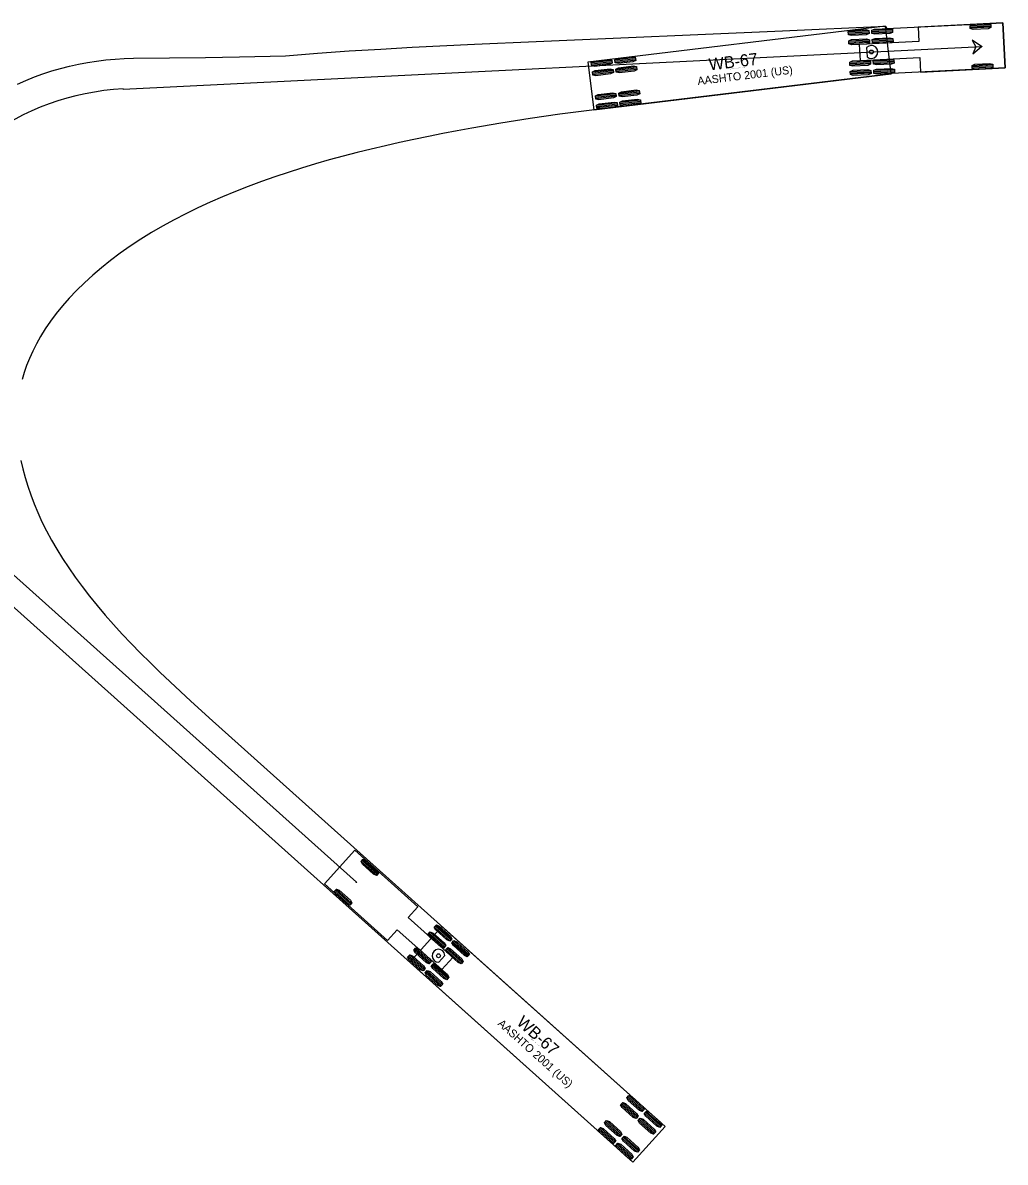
# Model space of a CAD drawing. Extents: x 1639988 to 1641860, y 841974 to 844187.
# Drawn here: x 1641686.5 to 1641860.3, y 841973.9 to 842175.6 of the extents above; entities that cross this region are included whole.
import ezdxf

# ---------------------------------------------------------------- set-up
doc = ezdxf.new("R2010")
doc.units = 0
doc.layers.add('Scratch_Level_1', color=7, linetype='Continuous')

msp = doc.modelspace()

# ---------------------------------------------------------------- linework, layer by layer
at = {"layer": 'Scratch_Level_1'}
for p, q in [((1641859.9, 842175.59), (1641844.91, 842174.84)), ((1641860.29, 842167.6), (1641859.9, 842175.59)), ((1641859.9, 842175.59), (1641859.9, 842175.59)), ((1641839.09, 842175.01), (1641786.47, 842168.65)), ((1641836.19, 842174.18), (1641832.52, 842174)), ((1641836.2, 842173.95), (1641832.54, 842173.77)), ((1641836.21, 842173.72), (1641832.55, 842173.54)), ((1641840.35, 842174.39), (1641836.69, 842174.21)), ((1641840.36, 842174.16), (1641836.7, 842173.98)), ((1641840.37, 842173.93), (1641836.71, 842173.75)), ((1641840.11, 842166.57), (1641839.09, 842175.01)), ((1641839.09, 842175.01), (1641839.09, 842175.01)), ((1641844.91, 842174.84), (1641845.04, 842172.28)), ((1641857.74, 842175.25), (1641854.08, 842175.07)), ((1641857.75, 842175.02), (1641854.09, 842174.84)), ((1641857.77, 842174.8), (1641854.1, 842174.61)), ((1641836.27, 842172.53), (1641832.61, 842172.35)), ((1641836.28, 842172.3), (1641832.62, 842172.12)), ((1641836.29, 842172.08), (1641832.63, 842171.89)), ((1641845.04, 842172.28), (1641834.47, 842171.76)), ((1641834.47, 842171.76), (1641834.61, 842168.89)), ((1641840.43, 842172.74), (1641836.77, 842172.56)), ((1641840.44, 842172.51), (1641836.78, 842172.33)), ((1641840.45, 842172.28), (1641836.79, 842172.1)), ((1641704.24, 842163.87), (1641856.1, 842171.4)), ((1641794.86, 842169.43), (1641791.22, 842168.99)), ((1641834.61, 842168.89), (1641845.18, 842169.42)), ((1641835.78, 842171.19), (1641835.86, 842169.58)), ((1641845.18, 842169.42), (1641845.31, 842166.85)), ((1641786.47, 842168.65), (1641787.49, 842160.21)), ((1641790.72, 842168.93), (1641787.08, 842168.49)), ((1641790.75, 842168.7), (1641787.11, 842168.26)), ((1641790.78, 842168.47), (1641787.14, 842168.03)), ((1641794.89, 842169.2), (1641791.24, 842168.76)), ((1641794.91, 842168.97), (1641791.27, 842168.53)), ((1641795.06, 842167.79), (1641791.42, 842167.35)), ((1641795.08, 842167.56), (1641791.44, 842167.12)), ((1641836.46, 842168.75), (1641832.79, 842168.57)), ((1641836.47, 842168.53), (1641832.81, 842168.34)), ((1641836.48, 842168.3), (1641832.82, 842168.11)), ((1641840.62, 842168.96), (1641836.96, 842168.78)), ((1641840.63, 842168.73), (1641836.97, 842168.55)), ((1641840.64, 842168.5), (1641836.98, 842168.32)), ((1641845.31, 842166.85), (1641860.29, 842167.6)), ((1641858.09, 842168.18), (1641854.43, 842168)), ((1641858.11, 842167.95), (1641854.44, 842167.77)), ((1641858.12, 842167.72), (1641854.45, 842167.54)), ((1641790.92, 842167.29), (1641787.28, 842166.85)), ((1641790.95, 842167.06), (1641787.31, 842166.62)), ((1641790.97, 842166.84), (1641787.33, 842166.4)), ((1641787.49, 842160.21), (1641840.11, 842166.57)), ((1641795.11, 842167.34), (1641791.47, 842166.9)), ((1641836.54, 842167.11), (1641832.88, 842166.92)), ((1641836.55, 842166.88), (1641832.89, 842166.7)), ((1641836.56, 842166.65), (1641832.9, 842166.47)), ((1641840.7, 842167.31), (1641837.04, 842167.13)), ((1641840.71, 842167.08), (1641837.05, 842166.9)), ((1641840.72, 842166.86), (1641837.06, 842166.67)), ((1641795.57, 842163.54), (1641791.93, 842163.1)), ((1641791.43, 842163.04), (1641787.79, 842162.6)), ((1641791.46, 842162.81), (1641787.82, 842162.37)), ((1641791.49, 842162.58), (1641787.85, 842162.14)), ((1641791.63, 842161.4), (1641787.99, 842160.96)), ((1641795.6, 842163.31), (1641791.96, 842162.87)), ((1641795.62, 842163.08), (1641791.98, 842162.64)), ((1641795.77, 842161.9), (1641792.13, 842161.46)), ((1641795.8, 842161.67), (1641792.15, 842161.23)), ((1641795.82, 842161.45), (1641792.18, 842161.01)), ((1641791.66, 842161.17), (1641788.02, 842160.73)), ((1641791.69, 842160.95), (1641788.05, 842160.51)), ((1641745.52, 842023.49), (1641676.43, 842085.42)), ((1641745.21, 842029.14), (1641739.87, 842023.18)), ((1641756.38, 842019.13), (1641745.21, 842029.14)), ((1641746.37, 842027.18), (1641749.1, 842024.74)), ((1641746.52, 842027.35), (1641749.25, 842024.91)), ((1641746.67, 842027.53), (1641749.4, 842025.08)), ((1641739.87, 842023.18), (1641751.04, 842013.17)), ((1641739.87, 842023.18), (1641739.87, 842023.18)), ((1641741.94, 842022.25), (1641744.67, 842019.8)), ((1641741.64, 842021.91), (1641744.37, 842019.46)), ((1641741.79, 842022.08), (1641744.52, 842019.63)), ((1641754.67, 842017.22), (1641756.38, 842019.13)), ((1641762.55, 842010.16), (1641754.67, 842017.22)), ((1641751.04, 842013.17), (1641752.75, 842015.08)), ((1641752.75, 842015.08), (1641760.64, 842008.02)), ((1641760.64, 842015.65), (1641754.97, 842009.32)), ((1641758.23, 842014.33), (1641760.96, 842011.88)), ((1641758.39, 842014.5), (1641761.12, 842012.05)), ((1641758.54, 842014.67), (1641761.27, 842012.22)), ((1641759.34, 842015.56), (1641762.07, 842013.11)), ((1641759.49, 842015.73), (1641762.22, 842013.28)), ((1641759.64, 842015.9), (1641762.37, 842013.45)), ((1641800.11, 841980.27), (1641760.64, 842015.65)), ((1641762.44, 842012.78), (1641765.17, 842010.33)), ((1641762.59, 842012.95), (1641765.32, 842010.5)), ((1641762.74, 842013.12), (1641765.47, 842010.67)), ((1641754.61, 842010.28), (1641757.34, 842007.84)), ((1641754.76, 842010.46), (1641757.49, 842008.01)), ((1641754.91, 842010.63), (1641757.64, 842008.18)), ((1641755.71, 842011.51), (1641758.44, 842009.07)), ((1641755.86, 842011.68), (1641758.59, 842009.24)), ((1641756.01, 842011.85), (1641758.75, 842009.41)), ((1641760.1, 842009.34), (1641761.18, 842010.54)), ((1641760.64, 842008.02), (1641762.55, 842010.16)), ((1641761.34, 842011.55), (1641764.07, 842009.1)), ((1641761.49, 842011.72), (1641764.22, 842009.27)), ((1641761.64, 842011.89), (1641764.37, 842009.44)), ((1641754.97, 842009.32), (1641794.44, 841973.94)), ((1641754.97, 842009.32), (1641754.97, 842009.32)), ((1641758.81, 842008.73), (1641761.54, 842006.29)), ((1641758.96, 842008.9), (1641761.7, 842006.46)), ((1641759.12, 842009.07), (1641761.85, 842006.63)), ((1641757.71, 842007.5), (1641760.44, 842005.06)), ((1641757.86, 842007.67), (1641760.59, 842005.23)), ((1641758.02, 842007.84), (1641760.75, 842005.4)), ((1641792.28, 841984.15), (1641795.01, 841981.7)), ((1641792.44, 841984.32), (1641795.17, 841981.87)), ((1641792.59, 841984.49), (1641795.32, 841982.04)), ((1641793.38, 841985.38), (1641796.11, 841982.93)), ((1641793.54, 841985.55), (1641796.27, 841983.1)), ((1641793.69, 841985.72), (1641796.42, 841983.27)), ((1641796.49, 841982.6), (1641799.22, 841980.15)), ((1641796.64, 841982.77), (1641799.37, 841980.32)), ((1641796.79, 841982.94), (1641799.52, 841980.49)), ((1641788.48, 841979.9), (1641791.21, 841977.45)), ((1641788.63, 841980.07), (1641791.36, 841977.62)), ((1641789.42, 841980.96), (1641792.15, 841978.51)), ((1641789.58, 841981.13), (1641792.31, 841978.68)), ((1641789.73, 841981.3), (1641792.46, 841978.85)), ((1641794.44, 841973.94), (1641800.11, 841980.27)), ((1641795.39, 841981.37), (1641798.12, 841978.92)), ((1641795.54, 841981.54), (1641798.27, 841979.09)), ((1641795.69, 841981.71), (1641798.42, 841979.26)), ((1641788.32, 841979.73), (1641791.05, 841977.28)), ((1641792.53, 841978.18), (1641795.26, 841975.73)), ((1641792.68, 841978.35), (1641795.41, 841975.9)), ((1641792.83, 841978.52), (1641795.56, 841976.07)), ((1641791.43, 841976.95), (1641794.16, 841974.5)), ((1641791.58, 841977.12), (1641794.31, 841974.67)), ((1641791.73, 841977.29), (1641794.46, 841974.84))]:
    msp.add_line(p, q, dxfattribs=at)
for points in [[(1641685.55, 842164.74), (1641687.03, 842165.4), (1641688.54, 842166), (1641690.07, 842166.55), (1641691.61, 842167.06), (1641693.17, 842167.51), (1641694.75, 842167.92), (1641696.34, 842168.27), (1641697.94, 842168.57), (1641699.55, 842168.82), (1641701.18, 842169.02), (1641702.81, 842169.17), (1641704.45, 842169.26), (1641706.1, 842169.3), (1641718.81, 842169.46), (1641724.86, 842169.57), (1641732.95, 842169.77), (1641738.63, 842170.21), (1641744.26, 842170.6), (1641749.85, 842170.95), (1641755.39, 842171.26), (1641766.39, 842171.8), (1641777.3, 842172.3), (1641820.89, 842174.19), (1641839.09, 842175.01), (1641839.37, 842174.57), (1641859.9, 842175.59), (1641860.29, 842167.6), (1641840.25, 842166.6), (1641840.11, 842166.57), (1641792.31, 842160.79), (1641786.72, 842160.09), (1641781.49, 842159.39), (1641776.28, 842158.64), (1641771.09, 842157.82), (1641765.93, 842156.94), (1641763.36, 842156.48), (1641760.79, 842155.99), (1641758.24, 842155.49), (1641755.7, 842154.96), (1641753.16, 842154.41), (1641750.64, 842153.84), (1641748.13, 842153.25), (1641745.64, 842152.63), (1641743.16, 842151.98), (1641740.7, 842151.31), (1641738.26, 842150.6), (1641735.83, 842149.87), (1641733.43, 842149.11), (1641731.06, 842148.31), (1641728.71, 842147.48), (1641726.39, 842146.62), (1641724.11, 842145.72), (1641721.85, 842144.79), (1641719.64, 842143.82), (1641717.47, 842142.82), (1641715.34, 842141.78), (1641713.26, 842140.7), (1641711.24, 842139.59), (1641709.27, 842138.45), (1641707.36, 842137.27), (1641705.51, 842136.05), (1641703.74, 842134.81), (1641702.03, 842133.54), (1641700.4, 842132.25), (1641698.86, 842130.93), (1641697.39, 842129.59), (1641696.01, 842128.24), (1641694.72, 842126.88), (1641693.53, 842125.52), (1641692.42, 842124.15), (1641691.41, 842122.79), (1641690.48, 842121.44), (1641689.65, 842120.1), (1641688.91, 842118.78), (1641688.25, 842117.48), (1641687.68, 842116.2), (1641687.18, 842114.94), (1641686.75, 842113.7), (1641686.4, 842112.47)], [(1641856.1, 842171.4), (1641854.45, 842172.53), (1641855.1, 842171.35), (1641854.57, 842170.1), (1641856.1, 842171.4)], [(1641686.17, 842098.12), (1641686.5, 842096.64), (1641686.9, 842095.13), (1641687.36, 842093.6), (1641687.89, 842092.05), (1641688.48, 842090.48), (1641689.15, 842088.9), (1641689.89, 842087.3), (1641690.69, 842085.68), (1641691.57, 842084.05), (1641692.52, 842082.42), (1641693.53, 842080.77), (1641694.62, 842079.12), (1641695.78, 842077.46), (1641697, 842075.8), (1641698.29, 842074.13), (1641699.65, 842072.46), (1641701.07, 842070.78), (1641702.54, 842069.1), (1641704.08, 842067.42), (1641705.68, 842065.74), (1641707.32, 842064.05), (1641709.02, 842062.36), (1641710.76, 842060.66), (1641712.55, 842058.95), (1641716.24, 842055.52), (1641720.05, 842052.04), (1641800.11, 841980.27), (1641794.44, 841973.94), (1641794.35, 841974.02), (1641794.35, 841974.02)], [(1641794.35, 841974.02), (1641683.3, 842073.57)]]:
    msp.add_lwpolyline(points, dxfattribs=at)
for points in [[(1641836.18, 842174.24), (1641836.21, 842173.67), (1641835.71, 842173.47), (1641833.07, 842173.34), (1641832.55, 842173.48), (1641832.52, 842174.06), (1641833.03, 842174.25), (1641835.66, 842174.38)], [(1641840.34, 842174.45), (1641840.37, 842173.87), (1641839.87, 842173.68), (1641837.23, 842173.55), (1641836.71, 842173.69), (1641836.68, 842174.26), (1641837.19, 842174.46), (1641839.82, 842174.59)], [(1641857.74, 842175.31), (1641857.77, 842174.74), (1641857.26, 842174.54), (1641854.63, 842174.41), (1641854.11, 842174.56), (1641854.08, 842175.13), (1641854.58, 842175.33), (1641857.22, 842175.46)], [(1641836.26, 842172.59), (1641836.29, 842172.02), (1641835.79, 842171.82), (1641833.15, 842171.69), (1641832.63, 842171.84), (1641832.6, 842172.41), (1641833.11, 842172.61), (1641835.74, 842172.74)], [(1641840.43, 842172.8), (1641840.45, 842172.23), (1641839.95, 842172.03), (1641837.31, 842171.9), (1641836.79, 842172.04), (1641836.76, 842172.62), (1641837.27, 842172.81), (1641839.91, 842172.94)], [(1641856.1, 842171.4), (1641854.45, 842172.53), (1641855.1, 842171.35), (1641854.57, 842170.1)], [(1641794.85, 842169.49), (1641794.92, 842168.92), (1641794.43, 842168.69), (1641791.81, 842168.37), (1641791.28, 842168.48), (1641791.21, 842169.05), (1641791.7, 842169.28), (1641794.32, 842169.6)], [(1641790.71, 842168.99), (1641790.78, 842168.42), (1641790.29, 842168.19), (1641787.67, 842167.87), (1641787.14, 842167.98), (1641787.07, 842168.55), (1641787.56, 842168.78), (1641790.18, 842169.1)], [(1641790.91, 842167.35), (1641790.98, 842166.78), (1641790.49, 842166.55), (1641787.87, 842166.23), (1641787.34, 842166.34), (1641787.27, 842166.91), (1641787.76, 842167.14), (1641790.38, 842167.46)], [(1641795.05, 842167.85), (1641795.12, 842167.28), (1641794.63, 842167.05), (1641792.01, 842166.73), (1641791.48, 842166.84), (1641791.41, 842167.41), (1641791.9, 842167.64), (1641794.52, 842167.96)], [(1641836.45, 842168.81), (1641836.48, 842168.24), (1641835.98, 842168.04), (1641833.34, 842167.91), (1641832.82, 842168.06), (1641832.79, 842168.63), (1641833.29, 842168.83), (1641835.93, 842168.96)], [(1641840.61, 842169.02), (1641840.64, 842168.45), (1641840.14, 842168.25), (1641837.5, 842168.12), (1641836.98, 842168.27), (1641836.95, 842168.84), (1641837.46, 842169.03), (1641840.09, 842169.17)], [(1641840.7, 842167.37), (1641840.72, 842166.8), (1641840.22, 842166.6), (1641837.58, 842166.47), (1641837.06, 842166.62), (1641837.03, 842167.19), (1641837.54, 842167.39), (1641840.18, 842167.52)], [(1641858.09, 842168.24), (1641858.12, 842167.66), (1641857.62, 842167.47), (1641854.98, 842167.34), (1641854.46, 842167.48), (1641854.43, 842168.05), (1641854.93, 842168.25), (1641857.57, 842168.38)], [(1641836.53, 842167.16), (1641836.56, 842166.59), (1641836.06, 842166.39), (1641833.42, 842166.26), (1641832.9, 842166.41), (1641832.87, 842166.98), (1641833.38, 842167.18), (1641836.01, 842167.31)], [(1641795.56, 842163.6), (1641795.63, 842163.03), (1641795.14, 842162.79), (1641792.52, 842162.48), (1641791.99, 842162.59), (1641791.92, 842163.16), (1641792.41, 842163.39), (1641795.03, 842163.7)], [(1641791.43, 842163.1), (1641791.49, 842162.53), (1641791.01, 842162.29), (1641788.38, 842161.98), (1641787.85, 842162.09), (1641787.79, 842162.66), (1641788.27, 842162.89), (1641790.9, 842163.2)], [(1641791.62, 842161.46), (1641791.69, 842160.89), (1641791.2, 842160.66), (1641788.58, 842160.34), (1641788.05, 842160.45), (1641787.98, 842161.02), (1641788.47, 842161.25), (1641791.09, 842161.57)], [(1641795.76, 842161.96), (1641795.83, 842161.39), (1641795.34, 842161.16), (1641792.72, 842160.84), (1641792.19, 842160.95), (1641792.12, 842161.52), (1641792.61, 842161.75), (1641795.23, 842162.07)], [(1641746.33, 842027.14), (1641746.71, 842027.57), (1641747.21, 842027.35), (1641749.17, 842025.59), (1641749.44, 842025.12), (1641749.06, 842024.69), (1641748.56, 842024.91), (1641746.6, 842026.67)], [(1641741.6, 842021.87), (1641741.98, 842022.29), (1641742.48, 842022.08), (1641744.45, 842020.32), (1641744.71, 842019.85), (1641744.33, 842019.42), (1641743.83, 842019.63), (1641741.87, 842021.4)], [(1641758.2, 842014.29), (1641758.58, 842014.71), (1641759.08, 842014.5), (1641761.04, 842012.74), (1641761.31, 842012.27), (1641760.93, 842011.84), (1641760.43, 842012.06), (1641758.46, 842013.82)], [(1641759.3, 842015.52), (1641759.68, 842015.94), (1641760.18, 842015.73), (1641762.14, 842013.97), (1641762.41, 842013.5), (1641762.03, 842013.07), (1641761.53, 842013.28), (1641759.56, 842015.05)], [(1641762.4, 842012.74), (1641762.78, 842013.16), (1641763.28, 842012.95), (1641765.25, 842011.19), (1641765.51, 842010.71), (1641765.13, 842010.29), (1641764.63, 842010.5), (1641762.67, 842012.27)], [(1641754.57, 842010.24), (1641754.95, 842010.67), (1641755.45, 842010.45), (1641757.41, 842008.69), (1641757.68, 842008.22), (1641757.3, 842007.8), (1641756.8, 842008.01), (1641754.84, 842009.77)], [(1641755.67, 842011.47), (1641756.05, 842011.9), (1641756.55, 842011.68), (1641758.52, 842009.92), (1641758.78, 842009.45), (1641758.4, 842009.02), (1641757.9, 842009.24), (1641755.94, 842011)], [(1641761.3, 842011.51), (1641761.68, 842011.93), (1641762.18, 842011.72), (1641764.14, 842009.96), (1641764.41, 842009.49), (1641764.03, 842009.06), (1641763.53, 842009.27), (1641761.57, 842011.04)], [(1641758.77, 842008.69), (1641759.16, 842009.12), (1641759.65, 842008.9), (1641761.62, 842007.14), (1641761.89, 842006.67), (1641761.5, 842006.24), (1641761.01, 842006.46), (1641759.04, 842008.22)], [(1641757.67, 842007.46), (1641758.05, 842007.89), (1641758.55, 842007.67), (1641760.52, 842005.91), (1641760.78, 842005.44), (1641760.4, 842005.01), (1641759.91, 842005.23), (1641757.94, 842006.99)], [(1641792.25, 841984.11), (1641792.63, 841984.53), (1641793.12, 841984.32), (1641795.09, 841982.56), (1641795.36, 841982.08), (1641794.98, 841981.66), (1641794.48, 841981.87), (1641792.51, 841983.63)], [(1641793.35, 841985.33), (1641793.73, 841985.76), (1641794.23, 841985.55), (1641796.19, 841983.78), (1641796.46, 841983.31), (1641796.08, 841982.89), (1641795.58, 841983.1), (1641793.61, 841984.86)], [(1641796.45, 841982.55), (1641796.83, 841982.98), (1641797.33, 841982.77), (1641799.29, 841981), (1641799.56, 841980.53), (1641799.18, 841980.11), (1641798.68, 841980.32), (1641796.72, 841982.08)], [(1641788.28, 841979.69), (1641788.67, 841980.11), (1641789.16, 841979.9), (1641791.13, 841978.14), (1641791.4, 841977.67), (1641791.02, 841977.24), (1641790.52, 841977.45), (1641788.55, 841979.22)], [(1641789.39, 841980.92), (1641789.77, 841981.34), (1641790.27, 841981.13), (1641792.23, 841979.37), (1641792.5, 841978.89), (1641792.12, 841978.47), (1641791.62, 841978.68), (1641789.65, 841980.45)], [(1641795.35, 841981.32), (1641795.73, 841981.75), (1641796.23, 841981.54), (1641798.19, 841979.77), (1641798.46, 841979.3), (1641798.08, 841978.88), (1641797.58, 841979.09), (1641795.62, 841980.85)], [(1641792.49, 841978.14), (1641792.87, 841978.56), (1641793.37, 841978.35), (1641795.33, 841976.58), (1641795.6, 841976.11), (1641795.22, 841975.69), (1641794.72, 841975.9), (1641792.76, 841977.66)], [(1641791.39, 841976.91), (1641791.77, 841977.33), (1641792.27, 841977.12), (1641794.23, 841975.36), (1641794.5, 841974.89), (1641794.12, 841974.46), (1641793.62, 841974.67), (1641791.65, 841976.44)]]:
    msp.add_lwpolyline(points, close=True, dxfattribs=at)
for centre, radius in [((1641856.1, 842171.4), 0.0417), ((1641836.62, 842170.43), 0.34), ((1641704.24, 842163.87), 0.0417), ((1641704.24, 842163.87), 0.0417), ((1641745.52, 842023.49), 0.0417), ((1641760.04, 842010.48), 0.34)]:
    msp.add_circle(centre, radius, dxfattribs=at)
for centre, radius, start, end in [((1641836.62, 842170.43), 1.14, 227.8475, 137.8475), ((1641706.47, 842118.93), 45, 92.836, 228.13), ((1641760.04, 842010.48), 1.14, 3.13, 273.13)]:
    msp.add_arc(centre, radius, start, end, dxfattribs=at)

# ---------------------------------------------------------------- texts
for s, height, rotation, p in [('WB-67', 2.125, 6.8921, (1641808, 842167.14)), ('AASHTO 2001 (US)', 1.4167, 6.8921, (1641805.94, 842164.57)), ('(c) 2019 Transoft Solutions, Inc. All rights reserved.', 0.085, 6.8921, (1641811.58, 842167.36)), ('WB-67', 2.125, 318.13, (1641773.7, 841998.47)), ('AASHTO 2001 (US)', 1.4167, 318.13, (1641770.41, 841998.32)), ('(c) 2019 Transoft Solutions, Inc. All rights reserved.', 0.085, 318.13, (1641776.22, 841995.92))]:
    msp.add_text(s, height=height, rotation=rotation, dxfattribs=at).set_placement(p)

doc.saveas('drawing.dxf')
